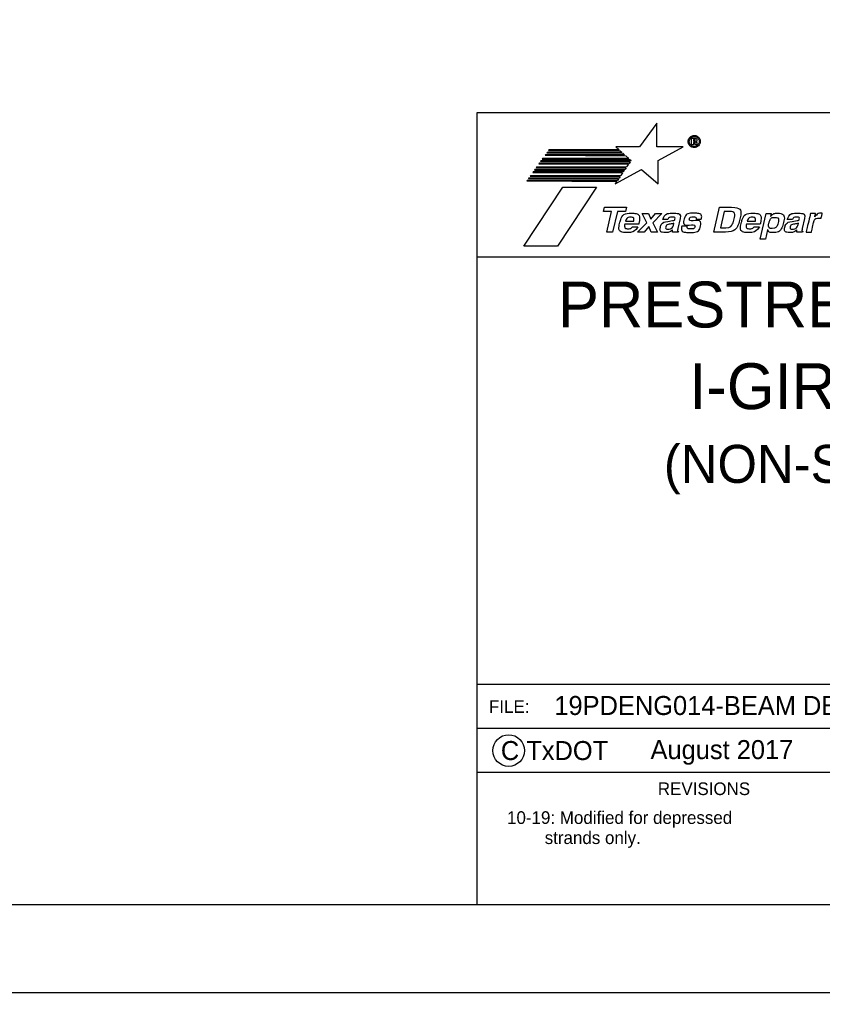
# Model space of a CAD drawing. Extents: x 998.6 to 1033.3, y 1000 to 1011.
# Drawn here: x 1012.425 to 1014.706, y 1000 to 1002.765 of the extents above; entities that cross this region are included whole.
import ezdxf

# ---------------------------------------------------------------- set-up
doc = ezdxf.new("R2010")
doc.units = 0
for name, color, linetype in [('D_BATCH_PLOT', 7, 'Continuous'), ('D_SHEET', 7, 'Continuous'), ('Working Level 1', 7, 'Continuous')]:
    doc.layers.add(name, color=color, linetype=linetype)

msp = doc.modelspace()

# ---------------------------------------------------------------- linework, layer by layer
at = {"layer": 'D_BATCH_PLOT'}
msp.add_lwpolyline([(1000, 1000), (1017, 1000), (1017, 1011), (1000, 1011)], close=True, dxfattribs=at)
at = {"layer": 'D_SHEET'}
for p, q in [((1013.725, 1000.25), (1013.725, 1002.5)), ((1013.725, 1002.5), (1016.75, 1002.5)), ((1014.2352, 1002.47), (1014.1865, 1002.4023)), ((1014.2352, 1002.4023), (1014.2352, 1002.47)), ((1013.9287, 1002.3939), (1013.9277, 1002.3925)), ((1013.9277, 1002.3925), (1014.1311, 1002.3915)), ((1014.128, 1002.3942), (1013.9287, 1002.3939)), ((1014.1865, 1002.4023), (1014.119, 1002.4023)), ((1014.119, 1002.4023), (1014.128, 1002.3942)), ((1014.128, 1002.3942), (1014.128, 1002.3942)), ((1014.1311, 1002.3915), (1014.1359, 1002.3872)), ((1014.3101, 1002.4023), (1014.2352, 1002.4023)), ((1014.2389, 1002.3638), (1014.3101, 1002.4023)), ((1014.3492, 1002.4118), (1014.3492, 1002.4101)), ((1013.9062, 1002.3625), (1013.9053, 1002.3612)), ((1014.1614, 1002.3628), (1013.9062, 1002.3625)), ((1013.9109, 1002.3691), (1013.91, 1002.3678)), ((1013.91, 1002.3678), (1014.1584, 1002.3671)), ((1014.1553, 1002.3699), (1013.9109, 1002.3691)), ((1013.9189, 1002.3802), (1013.9179, 1002.3789)), ((1013.9179, 1002.3789), (1014.1468, 1002.3774)), ((1014.1437, 1002.3802), (1013.9189, 1002.3802)), ((1013.9236, 1002.3869), (1013.9227, 1002.3856)), ((1013.9227, 1002.3856), (1014.1389, 1002.3845)), ((1014.1359, 1002.3872), (1013.9236, 1002.3869)), ((1014.1359, 1002.3872), (1014.1359, 1002.3872)), ((1014.1389, 1002.3845), (1014.1437, 1002.3802)), ((1014.1468, 1002.3774), (1014.1553, 1002.3699)), ((1014.1553, 1002.3699), (1014.1553, 1002.3699)), ((1014.1584, 1002.3671), (1014.1584, 1002.3671)), ((1014.1584, 1002.3671), (1014.1621, 1002.3638)), ((1014.1621, 1002.3638), (1014.1614, 1002.3628)), ((1014.2389, 1002.2979), (1014.2389, 1002.3638)), ((1013.8887, 1002.3381), (1013.8878, 1002.3368)), ((1013.8878, 1002.3368), (1014.143, 1002.3358)), ((1014.1448, 1002.3384), (1013.8887, 1002.3381)), ((1013.8937, 1002.3451), (1013.8928, 1002.3438)), ((1013.8928, 1002.3438), (1014.1478, 1002.3428)), ((1014.1496, 1002.3455), (1013.8937, 1002.3451)), ((1013.9014, 1002.3558), (1013.9005, 1002.3545)), ((1013.9005, 1002.3545), (1014.1547, 1002.353)), ((1013.9016, 1002.3558), (1013.9014, 1002.3558)), ((1014.1566, 1002.3557), (1013.9016, 1002.3558)), ((1013.9053, 1002.3612), (1014.1596, 1002.3601)), ((1014.1171, 1002.2979), (1014.1921, 1002.3382)), ((1014.143, 1002.3358), (1014.14, 1002.3315)), ((1014.1478, 1002.3428), (1014.1448, 1002.3384)), ((1014.1547, 1002.353), (1014.1496, 1002.3455)), ((1014.1596, 1002.3601), (1014.1566, 1002.3557)), ((1014.1921, 1002.3382), (1014.2389, 1002.2979)), ((1013.8665, 1002.307), (1013.8656, 1002.3058)), ((1014.1234, 1002.3071), (1013.8665, 1002.307)), ((1013.8712, 1002.3137), (1013.8703, 1002.3124)), ((1013.8703, 1002.3124), (1014.1263, 1002.3113)), ((1014.1281, 1002.314), (1013.8712, 1002.3137)), ((1013.8763, 1002.3207), (1013.8753, 1002.3194)), ((1013.8753, 1002.3194), (1014.131, 1002.3183)), ((1014.1329, 1002.3211), (1013.8763, 1002.3207)), ((1013.8839, 1002.3314), (1013.883, 1002.3301)), ((1013.883, 1002.3301), (1014.1381, 1002.3287)), ((1014.14, 1002.3315), (1013.8839, 1002.3314)), ((1014.1263, 1002.3113), (1014.1234, 1002.3071)), ((1014.131, 1002.3183), (1014.1281, 1002.314)), ((1014.1281, 1002.314), (1014.1281, 1002.314)), ((1014.131, 1002.3183), (1014.131, 1002.3183)), ((1014.133, 1002.3211), (1014.1329, 1002.3211)), ((1014.1381, 1002.3287), (1014.133, 1002.3211)), ((1013.8578, 1002.12), (1013.9684, 1002.2882)), ((1013.8656, 1002.3058), (1014.1215, 1002.3043)), ((1014.0641, 1002.2882), (1013.9535, 1002.12)), ((1013.9684, 1002.2882), (1014.0641, 1002.2882)), ((1014.1215, 1002.3043), (1014.1171, 1002.2979)), ((1014.1215, 1002.3043), (1014.1215, 1002.3043)), ((1014.0835, 1002.2186), (1014.0865, 1002.2311)), ((1014.0865, 1002.2311), (1014.1496, 1002.2311)), ((1014.1496, 1002.2311), (1014.1467, 1002.2186)), ((1014.107, 1002.2186), (1014.0835, 1002.2186)), ((1014.0934, 1002.1604), (1014.107, 1002.2186)), ((1014.1232, 1002.2186), (1014.1097, 1002.1604)), ((1014.1467, 1002.2186), (1014.1232, 1002.2186)), ((1014.2065, 1002.1871), (1014.1937, 1002.2128)), ((1014.1937, 1002.2128), (1014.2121, 1002.2128)), ((1014.2121, 1002.2128), (1014.2183, 1002.1975)), ((1014.2183, 1002.1975), (1014.2314, 1002.2128)), ((1014.2492, 1002.2128), (1014.2243, 1002.1871)), ((1014.2314, 1002.2128), (1014.2492, 1002.2128)), ((1014.3017, 1002.199), (1014.2951, 1002.1707)), ((1014.6552, 1002.199), (1014.6486, 1002.1707)), ((1014.1467, 1002.1918), (1014.1702, 1002.1918)), ((1014.1658, 1002.1758), (1014.1814, 1002.1758)), ((1014.1807, 1002.1604), (1014.2065, 1002.1871)), ((1014.2126, 1002.1762), (1014.199, 1002.1604)), ((1014.2189, 1002.1604), (1014.2126, 1002.1762)), ((1014.2243, 1002.1871), (1014.2376, 1002.1604)), ((1014.2669, 1002.1958), (1014.2523, 1002.1958)), ((1014.2661, 1002.191), (1014.2802, 1002.1929)), ((1014.2823, 1002.1792), (1014.2838, 1002.1859)), ((1014.4921, 1002.1918), (1014.5156, 1002.1918)), ((1014.5112, 1002.1758), (1014.5267, 1002.1758)), ((1014.6204, 1002.1958), (1014.6058, 1002.1958)), ((1014.6196, 1002.191), (1014.6336, 1002.1929)), ((1014.6357, 1002.1792), (1014.6373, 1002.1859)), ((1014.1097, 1002.1604), (1014.0934, 1002.1604)), ((1014.199, 1002.1604), (1014.1807, 1002.1604)), ((1014.2376, 1002.1604), (1014.2189, 1002.1604)), ((1013.9535, 1002.12), (1013.8578, 1002.12)), ((1013.725, 1002.09), (1016.75, 1002.09)), ((1016.75, 1000.875), (1013.725, 1000.875)), ((1016.75, 1000.75), (1013.725, 1000.75)), ((1016.75, 1000.625), (1013.725, 1000.625)), ((1001, 1000.25), (1016.75, 1000.25)), ((1000, 1000), (1017, 1000))]:
    msp.add_line(p, q, dxfattribs=at)
for points in [[(1014.3411, 1002.4151), (1014.3401, 1002.4151), (1014.339, 1002.4151), (1014.339, 1002.4085), (1014.3341, 1002.4085), (1014.3341, 1002.4272)], [(1014.3402, 1002.4239), (1014.339, 1002.4239), (1014.339, 1002.4185), (1014.3409, 1002.4185)], [(1014.3493, 1002.409), (1014.3495, 1002.4085), (1014.3448, 1002.4085)], [(1014.4306, 1002.1604), (1014.397, 1002.1604), (1014.4135, 1002.2311), (1014.4478, 1002.2311)], [(1014.4422, 1002.2189), (1014.4266, 1002.2189), (1014.4158, 1002.1726), (1014.4316, 1002.1726)], [(1014.5503, 1002.1671), (1014.55, 1002.1671), (1014.5437, 1002.1401), (1014.5286, 1002.1401), (1014.5456, 1002.2128), (1014.5601, 1002.2128), (1014.5583, 1002.2052), (1014.5585, 1002.2052)], [(1014.1843, 1002.1853), (1014.1837, 1002.1829), (1014.1442, 1002.1829)], [(1014.5296, 1002.1853), (1014.529, 1002.1829), (1014.4896, 1002.1829)], [(1014.2965, 1002.1625), (1014.2961, 1002.1604), (1014.2797, 1002.1604)], [(1014.65, 1002.1625), (1014.6495, 1002.1604), (1014.6332, 1002.1604)]]:
    msp.add_lwpolyline(points, dxfattribs=at)
msp.add_ellipse((1013.8146, 1000.6875), major_axis=(0.0449, 0), ratio=0.999082, dxfattribs=at)
for points, degree in [([(1014.3534, 1002.4058), (1014.3501, 1002.4026), (1014.3461, 1002.401), (1014.3415, 1002.401), (1014.3368, 1002.401), (1014.3328, 1002.4026), (1014.3295, 1002.4059), (1014.3263, 1002.4091), (1014.3246, 1002.4131), (1014.3246, 1002.4179), (1014.3246, 1002.4228), (1014.3264, 1002.4269), (1014.3299, 1002.4302), (1014.3308, 1002.431), (1014.3318, 1002.4318), (1014.3328, 1002.4324)], 3), ([(1014.3316, 1002.4277), (1014.3289, 1002.4249), (1014.3276, 1002.4217), (1014.3276, 1002.4179), (1014.3276, 1002.414), (1014.3289, 1002.4107), (1014.3317, 1002.4079), (1014.3344, 1002.4052), (1014.3377, 1002.4038), (1014.3415, 1002.4038), (1014.3454, 1002.4038), (1014.3486, 1002.4052), (1014.3514, 1002.4079), (1014.3541, 1002.4107), (1014.3555, 1002.414), (1014.3555, 1002.4179), (1014.3555, 1002.4217), (1014.3541, 1002.4249), (1014.3514, 1002.4277), (1014.3487, 1002.4305), (1014.3454, 1002.4319), (1014.3415, 1002.4319), (1014.3377, 1002.4319), (1014.3344, 1002.4305), (1014.3316, 1002.4277)], 3), ([(1014.3328, 1002.4324), (1014.3354, 1002.434), (1014.3383, 1002.4348), (1014.3415, 1002.4348), (1014.3462, 1002.4348), (1014.3502, 1002.4331), (1014.3535, 1002.4298), (1014.3568, 1002.4265), (1014.3584, 1002.4226), (1014.3584, 1002.4179), (1014.3584, 1002.4131), (1014.3567, 1002.4091), (1014.3534, 1002.4058)], 3), ([(1014.3341, 1002.4272), (1014.3353, 1002.4272), (1014.337, 1002.4272), (1014.3394, 1002.4272), (1014.3417, 1002.4272), (1014.343, 1002.4272), (1014.3432, 1002.4272), (1014.3447, 1002.4271), (1014.3459, 1002.4267), (1014.3469, 1002.4262), (1014.3486, 1002.4253), (1014.3494, 1002.4238), (1014.3494, 1002.4217), (1014.3494, 1002.4202), (1014.349, 1002.419), (1014.3481, 1002.4183), (1014.3472, 1002.4176), (1014.3461, 1002.4172), (1014.3448, 1002.4171)], 3), ([(1014.3431, 1002.4235), (1014.3424, 1002.4238), (1014.3415, 1002.4239), (1014.3402, 1002.4239)], 2), ([(1014.3409, 1002.4185), (1014.3421, 1002.4185), (1014.343, 1002.4187), (1014.3436, 1002.4192), (1014.3443, 1002.4196), (1014.3446, 1002.4204), (1014.3446, 1002.4214), (1014.3446, 1002.4224), (1014.3441, 1002.4231), (1014.3431, 1002.4235)], 3), ([(1014.3448, 1002.4085), (1014.3447, 1002.4091), (1014.3446, 1002.41), (1014.3445, 1002.4111), (1014.3444, 1002.4122), (1014.3444, 1002.413), (1014.3442, 1002.4134), (1014.344, 1002.414), (1014.3435, 1002.4145), (1014.3428, 1002.4148), (1014.3425, 1002.4149), (1014.3419, 1002.415), (1014.3411, 1002.4151)], 3), ([(1014.3448, 1002.4171), (1014.346, 1002.4168), (1014.3469, 1002.4165), (1014.3475, 1002.416), (1014.3486, 1002.4151), (1014.3492, 1002.4137), (1014.3492, 1002.4118)], 3), ([(1014.3492, 1002.4101), (1014.3492, 1002.4099), (1014.3492, 1002.4098), (1014.3492, 1002.4096), (1014.3492, 1002.4094), (1014.3493, 1002.4092), (1014.3493, 1002.409)], 3), ([(1014.4478, 1002.2311), (1014.474, 1002.2311), (1014.4747, 1002.2108), (1014.4715, 1002.1974), (1014.468, 1002.1823), (1014.4563, 1002.1604), (1014.4306, 1002.1604)], 3), ([(1014.1814, 1002.1758), (1014.1745, 1002.1632), (1014.162, 1002.1591), (1014.1522, 1002.1591), (1014.1359, 1002.1591), (1014.1252, 1002.1661), (1014.1302, 1002.1877), (1014.1317, 1002.194), (1014.1388, 1002.2141), (1014.164, 1002.2141), (1014.1753, 1002.2141), (1014.1899, 1002.2092), (1014.1843, 1002.1853)], 3), ([(1014.1702, 1002.1918), (1014.1713, 1002.2003), (1014.166, 1002.2028), (1014.1611, 1002.2028), (1014.154, 1002.2028), (1014.1492, 1002.1987), (1014.1467, 1002.1918)], 3), ([(1014.2523, 1002.1958), (1014.2578, 1002.2119), (1014.2705, 1002.2141), (1014.2823, 1002.2141), (1014.2904, 1002.2141), (1014.3047, 1002.2119), (1014.3017, 1002.199)], 3), ([(1014.2802, 1002.1929), (1014.2826, 1002.1932), (1014.2858, 1002.1941), (1014.2864, 1002.197), (1014.2878, 1002.2028), (1014.2818, 1002.2031), (1014.2779, 1002.2031), (1014.2703, 1002.2031), (1014.2681, 1002.1989), (1014.2669, 1002.1958)], 3), ([(1014.3471, 1002.1968), (1014.3472, 1002.2002), (1014.3468, 1002.2037), (1014.3385, 1002.2037), (1014.3303, 1002.2037), (1014.3286, 1002.2009), (1014.328, 1002.1986), (1014.3261, 1002.1903), (1014.3635, 1002.1963), (1014.359, 1002.1771), (1014.3555, 1002.1618), (1014.3386, 1002.1591), (1014.3296, 1002.1591), (1014.3165, 1002.1591), (1014.3033, 1002.1632), (1014.3061, 1002.1772), (1014.3061, 1002.1772), (1014.3217, 1002.1772), (1014.3217, 1002.1772), (1014.3207, 1002.1727), (1014.323, 1002.1695), (1014.3325, 1002.1695), (1014.3403, 1002.1695), (1014.3429, 1002.1729), (1014.3434, 1002.1749), (1014.3454, 1002.1836), (1014.3082, 1002.1771), (1014.3127, 1002.1966), (1014.3145, 1002.2043), (1014.3221, 1002.2141), (1014.3401, 1002.2141), (1014.3514, 1002.2141), (1014.3642, 1002.2116), (1014.3619, 1002.1968), (1014.3619, 1002.1968), (1014.3471, 1002.1968), (1014.3471, 1002.1968)], 3), ([(1014.4316, 1002.1726), (1014.4448, 1002.1726), (1014.452, 1002.1847), (1014.4547, 1002.1963), (1014.4596, 1002.2172), (1014.4491, 1002.2189), (1014.4422, 1002.2189)], 3), ([(1014.5267, 1002.1758), (1014.5198, 1002.1632), (1014.5074, 1002.1591), (1014.4975, 1002.1591), (1014.4813, 1002.1591), (1014.4705, 1002.1661), (1014.4755, 1002.1877), (1014.477, 1002.194), (1014.4841, 1002.2141), (1014.5093, 1002.2141), (1014.5207, 1002.2141), (1014.5352, 1002.2092), (1014.5296, 1002.1853)], 3), ([(1014.5156, 1002.1918), (1014.5167, 1002.2003), (1014.5113, 1002.2028), (1014.5065, 1002.2028), (1014.4993, 1002.2028), (1014.4946, 1002.1987), (1014.4921, 1002.1918)], 3), ([(1014.5585, 1002.2052), (1014.5623, 1002.2093), (1014.5676, 1002.2141), (1014.5778, 1002.2141), (1014.5905, 1002.2141), (1014.5996, 1002.2053), (1014.5954, 1002.1872), (1014.592, 1002.1728), (1014.5817, 1002.1591), (1014.5646, 1002.1591), (1014.554, 1002.1591), (1014.5514, 1002.1643), (1014.5503, 1002.1671)], 3), ([(1014.5634, 1002.1704), (1014.5732, 1002.1704), (1014.5782, 1002.18), (1014.5796, 1002.1862), (1014.5815, 1002.1945), (1014.5801, 1002.2022), (1014.5705, 1002.2022), (1014.5601, 1002.2022), (1014.5556, 1002.1938), (1014.5537, 1002.1854), (1014.5519, 1002.1777), (1014.5538, 1002.1704), (1014.5634, 1002.1704)], 3), ([(1014.6058, 1002.1958), (1014.6112, 1002.2119), (1014.624, 1002.2141), (1014.6358, 1002.2141), (1014.6439, 1002.2141), (1014.6582, 1002.2119), (1014.6552, 1002.199)], 3), ([(1014.6336, 1002.1929), (1014.6361, 1002.1932), (1014.6392, 1002.1941), (1014.6399, 1002.197), (1014.6413, 1002.2028), (1014.6353, 1002.2031), (1014.6314, 1002.2031), (1014.6238, 1002.2031), (1014.6215, 1002.1989), (1014.6204, 1002.1958)], 3), ([(1014.6716, 1002.2128), (1014.6716, 1002.2128), (1014.6861, 1002.2128), (1014.6861, 1002.2128), (1014.6861, 1002.2128), (1014.684, 1002.2037), (1014.684, 1002.2037), (1014.684, 1002.2037), (1014.6842, 1002.2037), (1014.6842, 1002.2037), (1014.6886, 1002.209), (1014.6932, 1002.2141), (1014.7024, 1002.2141), (1014.7034, 1002.2141), (1014.7043, 1002.214), (1014.7053, 1002.2139), (1014.7053, 1002.2139), (1014.702, 1002.2), (1014.702, 1002.2), (1014.7008, 1002.2002), (1014.6992, 1002.2002), (1014.6978, 1002.2002), (1014.686, 1002.2002), (1014.6822, 1002.1935), (1014.6809, 1002.1877), (1014.6809, 1002.1877), (1014.6745, 1002.1604), (1014.6745, 1002.1604), (1014.6745, 1002.1604), (1014.6594, 1002.1604), (1014.6594, 1002.1604), (1014.6594, 1002.1604), (1014.6716, 1002.2128), (1014.6716, 1002.2128)], 3), ([(1014.1442, 1002.1829), (1014.1437, 1002.1789), (1014.1425, 1002.1701), (1014.1547, 1002.1701), (1014.159, 1002.1701), (1014.1638, 1002.172), (1014.1658, 1002.1758)], 3), ([(1014.2798, 1002.1666), (1014.2756, 1002.1634), (1014.2697, 1002.1591), (1014.2594, 1002.1591), (1014.2507, 1002.1591), (1014.2429, 1002.1635), (1014.2454, 1002.1743), (1014.2478, 1002.1845), (1014.2562, 1002.1897), (1014.2661, 1002.191)], 3), ([(1014.2838, 1002.1859), (1014.2821, 1002.1848), (1014.2794, 1002.1839), (1014.2729, 1002.1831), (1014.2671, 1002.1822), (1014.2621, 1002.1809), (1014.2608, 1002.1752), (1014.2597, 1002.1704), (1014.2634, 1002.1689), (1014.2663, 1002.1689), (1014.2731, 1002.1689), (1014.2808, 1002.1728), (1014.2823, 1002.1792)], 3), ([(1014.2951, 1002.1707), (1014.2936, 1002.1645), (1014.2948, 1002.1631), (1014.2965, 1002.1625)], 2), ([(1014.4896, 1002.1829), (1014.4891, 1002.1789), (1014.4879, 1002.1701), (1014.5001, 1002.1701), (1014.5043, 1002.1701), (1014.5091, 1002.172), (1014.5112, 1002.1758)], 3), ([(1014.6332, 1002.1666), (1014.629, 1002.1634), (1014.6231, 1002.1591), (1014.6129, 1002.1591), (1014.6042, 1002.1591), (1014.5964, 1002.1635), (1014.5989, 1002.1743), (1014.6013, 1002.1845), (1014.6096, 1002.1897), (1014.6196, 1002.191)], 3), ([(1014.6373, 1002.1859), (1014.6355, 1002.1848), (1014.6328, 1002.1839), (1014.6264, 1002.1831), (1014.6205, 1002.1822), (1014.6156, 1002.1809), (1014.6142, 1002.1752), (1014.6131, 1002.1704), (1014.6169, 1002.1689), (1014.6198, 1002.1689), (1014.6265, 1002.1689), (1014.6342, 1002.1728), (1014.6357, 1002.1792)], 3), ([(1014.6486, 1002.1707), (1014.6471, 1002.1645), (1014.6483, 1002.1631), (1014.65, 1002.1625)], 2), ([(1014.2797, 1002.1604), (1014.2794, 1002.1629), (1014.2794, 1002.1637), (1014.2798, 1002.1666)], 2), ([(1014.6332, 1002.1604), (1014.6329, 1002.1629), (1014.6329, 1002.1637), (1014.6332, 1002.1666)], 2)]:
    msp.add_open_spline(points, degree=degree, dxfattribs=at)

# ---------------------------------------------------------------- texts
for s, height, p in [('19PDENG014-BEAM DESIGN.dgn', 0.053999, (1013.9442, 1000.7885)), ('C TxDOT', 0.05399, (1013.7922, 1000.6605)), ('August 2017   ', 0.054, (1014.2174, 1000.6632)), ('REVISIONS', 0.036, (1014.2382, 1000.561)), ('10-19: Modified for depressed ', 0.036, (1013.8098, 1000.479)), ('        strands only.', 0.036, (1013.8098, 1000.4219))]:
    msp.add_text(s, height=height, dxfattribs=at).set_placement(p)
msp.add_text('FILE:', height=0.036, rotation=360, dxfattribs=at).set_placement((1013.7585, 1000.7945))
at = {"layer": 'Working Level 1'}
for s, height, p in [('PRESTRESSED CONCRETE', 0.130498, (1013.9546, 1001.8894)), ('I-GIRDER DESIGNS', 0.1305, (1014.3276, 1001.6574)), ('(NON-STANDARD SPANS)', 0.107956, (1014.2552, 1001.448))]:
    msp.add_text(s, height=height, dxfattribs=at).set_placement(p)

doc.saveas('drawing.dxf')
